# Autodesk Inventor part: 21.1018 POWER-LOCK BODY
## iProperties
Created: 2006-12
Part Number: 21.1018 POWER-LOCK BODY
Document SubType Name: Modeling
Designer: Andy Moles
Material: Steel
Density: 7.85 g/cm^3
Mass: 12.9507 g
Surface Area: 17.6323 cm^2
Volume: 1.64977 cm^3
Author: Andy Moles
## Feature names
1. Extrusion1
2. Extrusion2
3. Mirror1
4. Extrusion3
5. Extrusion4
6. Extrusion5
